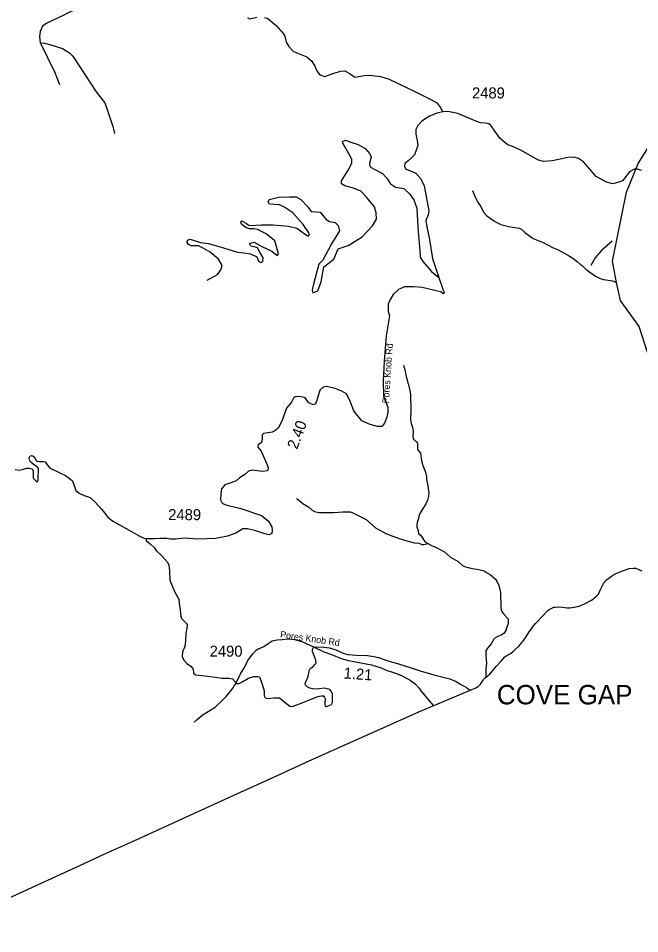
# Model space of a CAD drawing. Extents: x 1248224 to 1454986, y 825081 to 985870.
# Drawn here: x 1360464 to 1367503, y 835288 to 845654 of the extents above; entities that cross this region are included whole.
import ezdxf

# ---------------------------------------------------------------- set-up
doc = ezdxf.new("R2010")
doc.units = 0
for name, color, linetype in [('Exist Boundary Political CountyLine', 7, 'Continuous'), ('Exist Geographical Mountain Summit Label', 7, 'Continuous'), ('Exist Hydrographic Misc Water Feature', 7, 'Continuous'), ('Exist Road Non-System Type 51', 7, 'Continuous'), ('Exist Road Secondary Mileage Hundredths English Label', 7, 'Continuous'), ('Exist Road Secondary Type 41 Attributed', 7, 'Continuous'), ('Exist Road Secondary Type 51 Label', 7, 'Continuous'), ('Exist Road Secondary Type 51 Number Label', 7, 'Continuous')]:
    doc.layers.add(name, color=color, linetype=linetype)

msp = doc.modelspace()

# ---------------------------------------------------------------- linework, layer by layer
at = {"layer": 'Exist Boundary Political CountyLine'}
msp.add_lwpolyline([(1359469, 835288), (1361210, 836084), (1361453, 836195), (1361758, 836333), (1362980, 836891), (1363325, 837046), (1363802, 837265), (1364640, 837638), (1365003, 837799), (1365649, 838074), (1365667, 838084), (1365673, 838088), (1365683, 838095), (1365690, 838101), (1365700, 838113), (1365716, 838137), (1365723, 838147), (1365733, 838164), (1365739, 838172), (1365757, 838190), (1365768, 838198), (1365782, 838207), (1365796, 838219), (1365804, 838227), (1365821, 838245), (1365880, 838316), (1365929, 838371), (1365952, 838398), (1365976, 838422), (1366009, 838445), (1366039, 838462), (1366074, 838488), (1366094, 838505), (1366133, 838545), (1366192, 838613), (1366211, 838639), (1366252, 838706), (1366277, 838742), (1366289, 838758), (1366324, 838799), (1366347, 838825), (1366391, 838872), (1366410, 838893), (1366453, 838938), (1366463, 838948), (1366479, 838960), (1366508, 838975), (1366522, 838981), (1366534, 838985), (1366546, 838987), (1366580, 838988), (1366632, 838985), (1366678, 838980), (1366712, 838979), (1366736, 838981), (1366804, 838993), (1366838, 839005), (1366899, 839034), (1366948, 839061), (1366970, 839074), (1366996, 839094), (1367019, 839113), (1367029, 839125), (1367035, 839133), (1367046, 839153), (1367064, 839194), (1367083, 839232), (1367098, 839262), (1367126, 839297), (1367210, 839354), (1367288, 839390), (1367385, 839424), (1367429, 839429), (1367461, 839427), (1367529, 839397)], dxfattribs=at)
at = {"layer": 'Exist Hydrographic Misc Water Feature'}
for points in [[(1367590, 841870), (1367496, 842164), (1367286, 842460), (1367240, 842663), (1367196, 842905), (1367355, 843686), (1367487, 844009), (1367746, 844420)], [(1365610, 843704), (1365633, 843647), (1365671, 843567), (1365695, 843534), (1365739, 843455), (1365768, 843422), (1365823, 843379), (1365855, 843362), (1365862, 843354), (1365930, 843320), (1366021, 843298), (1366137, 843279), (1366169, 843263), (1366204, 843228), (1366259, 843185), (1366298, 843162), (1366409, 843117), (1366516, 843060), (1366572, 843037), (1366706, 842966), (1366729, 842945), (1366745, 842937), (1366800, 842896), (1366832, 842867), (1366855, 842850), (1366898, 842809), (1367001, 842735), (1367048, 842710), (1367068, 842703), (1367092, 842697), (1367194, 842682), (1367240, 842663)], [(1365610, 843704), (1365633, 843647), (1365671, 843567), (1365695, 843534), (1365739, 843455), (1365768, 843422), (1365823, 843379), (1365855, 843362), (1365862, 843354), (1365930, 843320), (1366021, 843298), (1366137, 843279), (1366169, 843263), (1366204, 843228), (1366259, 843185), (1366298, 843162), (1366409, 843117), (1366516, 843060), (1366572, 843037), (1366706, 842966), (1366729, 842945), (1366745, 842937), (1366800, 842896), (1366832, 842867), (1366855, 842850), (1366898, 842809), (1367001, 842735), (1367048, 842710), (1367068, 842703), (1367092, 842697), (1367194, 842682), (1367240, 842663)], [(1364829, 841727), (1364844, 841675), (1364857, 841598), (1364877, 841530), (1364877, 841522), (1364884, 841506), (1364901, 841437), (1364906, 841393), (1364906, 841321), (1364911, 841277), (1364912, 841213), (1364907, 841109), (1364916, 841065), (1364935, 841008), (1364939, 840980), (1364933, 840916), (1364937, 840898), (1364942, 840888), (1364976, 840859), (1364985, 840843), (1364988, 840771), (1365019, 840730), (1365031, 840646), (1365048, 840590), (1365072, 840525), (1365089, 840461), (1365090, 840437), (1365108, 840340), (1365108, 840324), (1365115, 840284), (1365112, 840244), (1365099, 840197), (1365080, 840157), (1365017, 840055), (1365003, 840015), (1364998, 839991), (1364981, 839943), (1364978, 839920), (1364980, 839897), (1364993, 839855), (1364998, 839819), (1365020, 839803), (1365037, 839784), (1365058, 839744), (1365068, 839731), (1365105, 839706)], [(1364829, 841727), (1364844, 841675), (1364857, 841598), (1364877, 841530), (1364877, 841522), (1364884, 841506), (1364901, 841437), (1364906, 841393), (1364906, 841321), (1364911, 841277), (1364912, 841213), (1364907, 841109), (1364916, 841065), (1364935, 841008), (1364939, 840980), (1364933, 840916), (1364937, 840898), (1364942, 840888), (1364976, 840859), (1364985, 840843), (1364988, 840771), (1365019, 840730), (1365031, 840646), (1365048, 840590), (1365072, 840525), (1365089, 840461), (1365090, 840437), (1365108, 840340), (1365108, 840324), (1365115, 840284), (1365112, 840244), (1365099, 840197), (1365080, 840157), (1365017, 840055), (1365003, 840015), (1364998, 839991), (1364981, 839943), (1364978, 839920), (1364980, 839897), (1364993, 839855), (1364998, 839819), (1365020, 839803), (1365037, 839784), (1365058, 839744), (1365068, 839731), (1365105, 839706)], [(1363615, 840212), (1363623, 840212), (1363686, 840158), (1363757, 840117), (1363792, 840084), (1363820, 840069), (1363867, 840056), (1364043, 840056), (1364140, 840066), (1364180, 840067), (1364224, 840064), (1364247, 840057), (1364406, 839977), (1364512, 839883), (1364634, 839818), (1364640, 839818), (1364666, 839805), (1364789, 839758), (1364852, 839739), (1364952, 839714), (1365000, 839709), (1365035, 839696), (1365059, 839696), (1365105, 839706)], [(1363615, 840212), (1363623, 840212), (1363686, 840158), (1363757, 840117), (1363792, 840084), (1363820, 840069), (1363867, 840056), (1364043, 840056), (1364140, 840066), (1364180, 840067), (1364224, 840064), (1364247, 840057), (1364406, 839977), (1364512, 839883), (1364634, 839818), (1364640, 839818), (1364666, 839805), (1364789, 839758), (1364852, 839739), (1364952, 839714), (1365000, 839709), (1365035, 839696), (1365059, 839696), (1365105, 839706)], [(1365105, 839706), (1365151, 839679), (1365175, 839671), (1365294, 839612), (1365364, 839550), (1365443, 839505), (1365498, 839459), (1365530, 839442), (1365609, 839423), (1365681, 839413), (1365729, 839400), (1365753, 839389), (1365768, 839377), (1365808, 839356), (1365871, 839304), (1365890, 839274), (1365909, 839233), (1365927, 839153), (1365929, 838985), (1365935, 838953), (1365942, 838937), (1365960, 838912), (1366012, 838855), (1366013, 838799), (1365990, 838736), (1365990, 838728), (1365981, 838712), (1365963, 838688), (1365946, 838675), (1365868, 838639), (1365851, 838625), (1365820, 838570), (1365781, 838523), (1365762, 838491), (1365761, 838437), (1365767, 838349), (1365762, 838293), (1365761, 838190)], [(1365105, 839706), (1365151, 839679), (1365175, 839671), (1365294, 839612), (1365364, 839550), (1365443, 839505), (1365498, 839459), (1365530, 839442), (1365609, 839423), (1365681, 839413), (1365729, 839400), (1365753, 839389), (1365768, 839377), (1365808, 839356), (1365871, 839304), (1365890, 839274), (1365909, 839233), (1365927, 839153), (1365929, 838985), (1365935, 838953), (1365942, 838937), (1365960, 838912), (1366012, 838855), (1366013, 838799), (1365990, 838736), (1365990, 838728), (1365981, 838712), (1365963, 838688), (1365946, 838675), (1365868, 838639), (1365851, 838625), (1365820, 838570), (1365781, 838523), (1365762, 838491), (1365761, 838437), (1365767, 838349), (1365762, 838293), (1365761, 838190)], [(1362457, 837684), (1362490, 837715), (1362547, 837762), (1362693, 837854), (1362783, 837936), (1362818, 837975), (1362871, 838038), (1362898, 838073), (1362915, 838105), (1362923, 838113), (1362984, 838237), (1363027, 838304), (1363038, 838330), (1363073, 838395), (1363123, 838458), (1363164, 838503), (1363180, 838513), (1363204, 838520), (1363245, 838539), (1363294, 838576), (1363342, 838603), (1363398, 838615), (1363455, 838618), (1363519, 838627), (1363565, 838625), (1363595, 838621), (1363676, 838597), (1363801, 838540), (1363924, 838479), (1364013, 838449), (1364122, 838406), (1364205, 838382), (1364464, 838334), (1364576, 838297), (1364631, 838274), (1364702, 838248), (1364736, 838240), (1364806, 838212), (1364903, 838160), (1364963, 838114), (1365006, 838067), (1365026, 838039), (1365121, 837920), (1365169, 837869)], [(1362457, 837684), (1362490, 837715), (1362547, 837762), (1362693, 837854), (1362783, 837936), (1362818, 837975), (1362871, 838038), (1362898, 838073), (1362915, 838105), (1362923, 838113), (1362984, 838237), (1363027, 838304), (1363038, 838330), (1363073, 838395), (1363123, 838458), (1363164, 838503), (1363180, 838513), (1363204, 838520), (1363245, 838539), (1363294, 838576), (1363342, 838603), (1363398, 838615), (1363455, 838618), (1363519, 838627), (1363565, 838625), (1363595, 838621), (1363676, 838597), (1363801, 838540), (1363924, 838479), (1364013, 838449), (1364122, 838406), (1364205, 838382), (1364464, 838334), (1364576, 838297), (1364631, 838274), (1364702, 838248), (1364736, 838240), (1364806, 838212), (1364903, 838160), (1364963, 838114), (1365006, 838067), (1365026, 838039), (1365121, 837920), (1365169, 837869)]]:
    msp.add_lwpolyline(points, dxfattribs=at)
at = {"layer": 'Exist Road Non-System Type 51'}
for points in [[(1361692, 846001), (1361601, 845948), (1361506, 845876), (1361403, 845813), (1361327, 845781), (1361264, 845771), (1361218, 845769), (1361173, 845767), (1361125, 845757), (1361030, 845714), (1360966, 845682), (1360786, 845597), (1360740, 845563), (1360711, 845503), (1360703, 845448), (1360713, 845378)], [(1363060, 845663), (1363088, 845647), (1363165, 845665)], [(1363255, 845663), (1363290, 845651), (1363384, 845572), (1363463, 845482), (1363485, 845453), (1363497, 845385), (1363530, 845334), (1363580, 845278), (1363637, 845254), (1363734, 845217), (1363788, 845167), (1363824, 845111), (1363849, 845052), (1363881, 845014), (1363937, 844996), (1364040, 845032), (1364117, 845056), (1364163, 845058), (1364222, 845024), (1364278, 844988), (1364385, 845008), (1364448, 845010), (1364567, 844996), (1364664, 844965), (1364948, 844828), (1365136, 844734), (1365206, 844695), (1365247, 844643), (1365267, 844601)], [(1360713, 845378), (1360877, 845039), (1360931, 844906)], [(1360713, 845378), (1360760, 845374), (1360834, 845352), (1360964, 845313), (1361044, 845261), (1361083, 845225), (1361155, 845114), (1361345, 844821), (1361444, 844698), (1361476, 844608), (1361534, 844428), (1361545, 844384), (1361553, 844350)], [(1364167, 844195), (1364141, 844239), (1364135, 844259), (1364170, 844274), (1364233, 844253), (1364314, 844224), (1364393, 844181), (1364445, 844120), (1364462, 844080), (1364442, 844010), (1364445, 843981), (1364462, 843964), (1364503, 843940), (1364590, 843897), (1364639, 843842), (1364679, 843781), (1364737, 843743), (1364833, 843726), (1364899, 843662), (1364946, 843598), (1364977, 843504), (1364986, 843362), (1364994, 843237), (1365012, 843026), (1365018, 842948), (1365047, 842901), (1365145, 842788), (1365228, 842718)], [(1362602, 842690), (1362720, 842751), (1362758, 842806), (1362773, 842856), (1362732, 842925), (1362639, 843006), (1362558, 843050), (1362506, 843076), (1362477, 843076), (1362422, 843079), (1362393, 843093), (1362376, 843116), (1362381, 843143), (1362413, 843151), (1362529, 843116), (1362619, 843102), (1362787, 843056), (1362949, 843006), (1363024, 843000), (1363094, 842986), (1363166, 842951), (1363187, 842902), (1363210, 842887), (1363236, 842902), (1363239, 842943), (1363204, 842998), (1363175, 843053), (1363135, 843067), (1363097, 843073), (1363085, 843102), (1363135, 843119), (1363224, 843070), (1363337, 843018), (1363398, 842969), (1363410, 842986), (1363372, 843134), (1363271, 843215), (1363175, 843261), (1363129, 843270), (1363082, 843270), (1363056, 843276), (1363019, 843299), (1362993, 843322), (1362987, 843351), (1362998, 843360), (1363051, 843331), (1363080, 843308), (1363219, 843314), (1363352, 843314), (1363526, 843299), (1363618, 843276), (1363728, 843200), (1363751, 843186), (1363763, 843212), (1363691, 843319), (1363575, 843450), (1363471, 843519), (1363424, 843543), (1363363, 843545), (1363311, 843551), (1363294, 843577), (1363305, 843603), (1363410, 843627), (1363537, 843632), (1363612, 843632), (1363665, 843603), (1363746, 843519), (1363783, 843467), (1363885, 843458), (1363950, 843377), (1363990, 843354), (1364054, 843342), (1364089, 843308), (1364103, 843247), (1364011, 843099), (1363915, 842916), (1363869, 842870), (1363811, 842658), (1363793, 842580), (1363799, 842545), (1363857, 842566), (1363895, 842670), (1363927, 842838), (1364037, 842925), (1364086, 843044), (1364202, 843082), (1364361, 843180), (1364477, 843302), (1364523, 843380), (1364520, 843450), (1364500, 843519), (1364410, 843629), (1364344, 843696), (1364260, 843731), (1364164, 843757), (1364126, 843780), (1364126, 843815), (1364202, 843934), (1364242, 844013), (1364242, 844059), (1364167, 844195)], [(1367190, 843129), (1367070, 843026), (1366999, 842941), (1366951, 842854)]]:
    msp.add_lwpolyline(points, dxfattribs=at)
at = {"layer": 'Exist Road Secondary Type 41 Attributed'}
for points in [[(1367523, 843929), (1367477, 843946), (1367445, 843946), (1367387, 843914), (1367309, 843812), (1367255, 843795), (1367199, 843780), (1367126, 843797), (1367009, 843863), (1366866, 844029), (1366809, 844068), (1366761, 844080), (1366688, 844078), (1366515, 844041), (1366415, 844034), (1366356, 844046), (1366149, 844163), (1366064, 844203), (1366010, 844220), (1365978, 844242), (1365920, 844298), (1365864, 844376), (1365820, 844437), (1365796, 844457), (1365757, 844467), (1365701, 844472), (1365649, 844489), (1365442, 844576), (1365330, 844598), (1365277, 844596), (1365204, 844581), (1365113, 844540), (1365033, 844484), (1364989, 844440), (1364967, 844394), (1364967, 844342), (1364982, 844272), (1364992, 844213), (1364972, 844159), (1364953, 844108), (1364919, 844072), (1364882, 844038), (1364843, 844011), (1364838, 843979), (1364853, 843947), (1364906, 843925), (1364967, 843899), (1365026, 843835), (1365062, 843755), (1365084, 843635), (1365113, 843474), (1365106, 843428), (1365082, 843364), (1365094, 843294), (1365118, 843167), (1365155, 842935), (1365228, 842718)], [(1365228, 842718), (1365264, 842611), (1365277, 842575), (1365287, 842553), (1365279, 842534), (1365250, 842556), (1365184, 842571), (1365038, 842605), (1364945, 842614), (1364841, 842612), (1364773, 842583), (1364712, 842527), (1364673, 842463), (1364656, 842417), (1364653, 842339), (1364670, 842285), (1364631, 842059), (1364610, 841770), (1364596, 841546), (1364600, 841375), (1364649, 841251), (1364652, 841193), (1364639, 841137), (1364613, 841069), (1364583, 841032), (1364535, 841030), (1364449, 841056), (1364354, 841095), (1364264, 841210), (1364228, 841307), (1364181, 841403), (1364130, 841432), (1364052, 841461), (1363957, 841483), (1363918, 841478), (1363879, 841442), (1363845, 841327), (1363831, 841288), (1363804, 841278), (1363755, 841298), (1363714, 841356), (1363667, 841368), (1363611, 841373), (1363587, 841359), (1363560, 841307)], [(1363560, 841307), (1363504, 841239), (1363448, 841091), (1363408, 841013), (1363369, 840983), (1363342, 840969), (1363296, 840961), (1363243, 840954), (1363225, 840939), (1363228, 840891), (1363218, 840852), (1363182, 840825), (1363179, 840796), (1363216, 840752), (1363284, 840597), (1363294, 840565), (1363286, 840531), (1363230, 840522), (1363108, 840536), (1363072, 840524), (1363026, 840485), (1362970, 840451), (1362931, 840417), (1362872, 840392), (1362804, 840370), (1362767, 840326), (1362758, 840273), (1362753, 840200), (1362775, 840163), (1362814, 840144), (1362984, 840102), (1363220, 840024), (1363298, 839961), (1363337, 839897), (1363342, 839857), (1363337, 839820), (1363308, 839806), (1363257, 839815), (1363155, 839852), (1363060, 839871), (1363006, 839871), (1362928, 839825), (1362833, 839788), (1362701, 839764), (1362499, 839757), (1362348, 839769), (1362250, 839754), (1362186, 839754), (1362147, 839764), (1362113, 839762), (1362072, 839762), (1362006, 839759), (1361962, 839759), (1361914, 839760)], [(1360678, 840401), (1360689, 840429), (1360692, 840557), (1360681, 840571), (1360632, 840605), (1360604, 840631), (1360590, 840654), (1360587, 840676), (1360599, 840701), (1360613, 840704), (1360629, 840698), (1360651, 840679), (1360662, 840649), (1360673, 840638), (1360703, 840634), (1360750, 840637), (1360767, 840632), (1360791, 840597), (1360816, 840569), (1360841, 840553), (1361000, 840476), (1361057, 840434), (1361077, 840417), (1361118, 840308), (1361154, 840275), (1361209, 840252), (1361278, 840227), (1361338, 840170), (1361405, 840101), (1361444, 840049), (1361473, 840008), (1361537, 839959), (1361721, 839859), (1361827, 839796), (1361870, 839774), (1361914, 839760)], [(1360428, 840545), (1360478, 840536), (1360522, 840547), (1360557, 840560), (1360585, 840560), (1360620, 840552), (1360634, 840527), (1360632, 840472), (1360634, 840446), (1360667, 840412), (1360678, 840401)], [(1361914, 839760), (1361913, 839741), (1361960, 839704), (1362009, 839657), (1362027, 839628), (1362090, 839567), (1362152, 839500), (1362170, 839467), (1362176, 839396), (1362180, 839293), (1362235, 839162), (1362282, 839076), (1362288, 839027), (1362294, 838987), (1362304, 838883), (1362314, 838858), (1362351, 838821), (1362376, 838793), (1362374, 838746), (1362361, 838690), (1362359, 838604), (1362349, 838539), (1362324, 838480), (1362320, 838427), (1362339, 838384), (1362375, 838347), (1362424, 838313), (1362445, 838282), (1362449, 838239), (1362471, 838219), (1362542, 838213), (1362671, 838196), (1362771, 838180), (1362850, 838182), (1362889, 838176), (1362922, 838141), (1362934, 838123), (1362966, 838123), (1362999, 838139), (1363073, 838182), (1363134, 838201), (1363174, 838201), (1363198, 838197), (1363228, 838115), (1363251, 838038), (1363249, 837981), (1363259, 837958), (1363296, 837950), (1363359, 837960)], [(1363359, 837960), (1363422, 837958), (1363489, 837905), (1363540, 837866), (1363567, 837860), (1363681, 837901), (1363858, 837974), (1363897, 837983), (1363920, 837981), (1363934, 837962), (1363944, 837940), (1363938, 837915), (1363938, 837890), (1363942, 837866), (1363960, 837862), (1363993, 837875), (1364013, 837884), (1364022, 837906), (1364023, 837949), (1364024, 838004), (1364010, 838035), (1363992, 838055), (1363932, 838067), (1363869, 838061), (1363811, 838058), (1363766, 838067), (1363736, 838082), (1363719, 838101), (1363713, 838119), (1363721, 838141), (1363739, 838180), (1363749, 838204), (1363755, 838237), (1363760, 838269), (1363772, 838291), (1363803, 838315), (1363825, 838335), (1363838, 838350), (1363834, 838387), (1363822, 838416), (1363796, 838483), (1363796, 838506), (1363808, 838530), (1363847, 838537), (1363922, 838532), (1363988, 838524), (1364062, 838501), (1364146, 838464), (1364192, 838451), (1364247, 838446), (1364294, 838443), (1364420, 838438), (1364492, 838428), (1364544, 838414), (1364650, 838380), (1364761, 838347), (1364926, 838295), (1365029, 838262), (1365097, 838241), (1365172, 838220), (1365247, 838201), (1365352, 838174), (1365425, 838143), (1365479, 838112), (1365514, 838091), (1365540, 838075), (1365582, 838045)]]:
    msp.add_lwpolyline(points, dxfattribs=at)

# ---------------------------------------------------------------- texts
at = {"layer": 'Exist Geographical Mountain Summit Label'}
msp.add_text('COVE GAP', height=220, dxfattribs=at).set_placement((1365885, 837885))
at = {"layer": 'Exist Road Secondary Mileage Hundredths English Label'}
for s, rotation, p in [('2.40', 69.3558, (1363622, 840765)), ('1.21', 355.8367, (1364146, 838179))]:
    msp.add_text(s, height=125, rotation=rotation, dxfattribs=at).set_placement(p)
at = {"layer": 'Exist Road Secondary Type 51 Label'}
for rotation, p in [(86.1689, (1364662, 841292)), (351.7855, (1363427, 838642))]:
    msp.add_text('Pores Knob Rd', height=75, rotation=rotation, dxfattribs=at).set_placement(p)
at = {"layer": 'Exist Road Secondary Type 51 Number Label'}
for s, p in [('2489', (1365604, 844746)), ('2489', (1362163, 839971)), ('2490', (1362632, 838425))]:
    msp.add_text(s, height=125, dxfattribs=at).set_placement(p)

doc.saveas('drawing.dxf')
